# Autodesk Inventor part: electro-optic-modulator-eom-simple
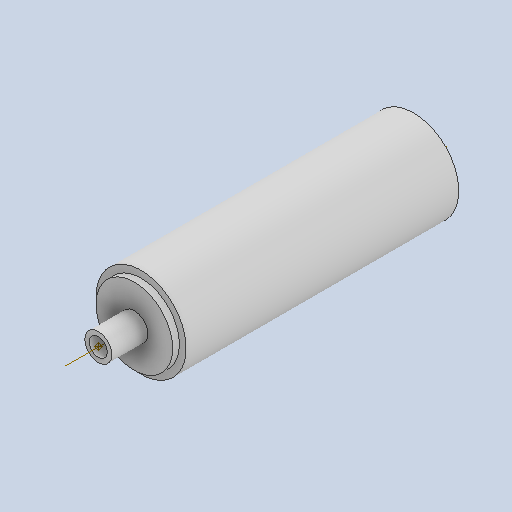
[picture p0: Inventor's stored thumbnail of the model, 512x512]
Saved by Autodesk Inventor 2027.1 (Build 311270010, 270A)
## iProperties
Created: 2026-07
Part Number: electro-optic-modulator-eom-simple
Material: Generic
Document SubType Name: Modeling
Designer: dunge
Density: 1 g/cm^3
Appearance: Default
Author: dunge
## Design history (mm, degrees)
sketch "Sketch1"
  geometry: L1 (12.7, 76.835)-(12.7, 0); L2 (12.7, 0)-(2.54, 0); L3 (2.54, 0)-(2.54, 88.9); L4 (2.54, 88.9)-(3.81, 88.9); L5 (3.81, 88.9)-(3.81, 78.74); L6 (3.81, 78.74)-(10.795, 78.74); L7 (10.795, 78.74)-(10.795, 76.835); L8 (10.795, 76.835)-(12.7, 76.835); L9 (0, 0)-(0, 88.9)
  constraints: 19 end point, 7 perpendicular, 2 vertical, 1 horizontal alignment
  dimensions: "d1" = 88.9 distance of L2.end L3.end; "d2" = 10.16 distance of L4.end L5.end; "d3" = 1.905 distance of L6.end L7.end; "d4" = 1.27 distance of L3.end L4.end; "d5" = 1.905 distance of L7.end L1.start; "d7" = 2.54 distance from line of L9.start L3; "d8" = 12.7 distance from line of L9.start L1
revolve "Revolution1" sketch "Sketch1" stored, may be unused: angle "d6" = 360 deg
workpoint "Work Point1"
  workaxis "Work Axis1"
body "Solid1"
